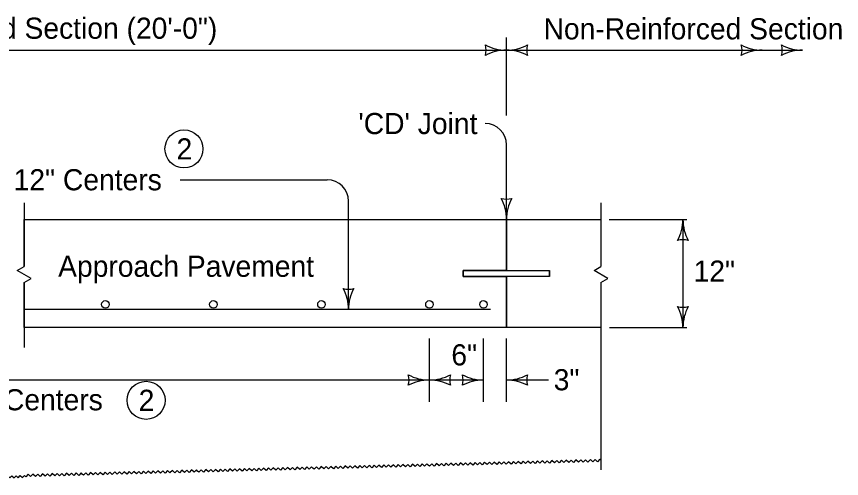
# Model space of a CAD drawing. Extents: x 8925 to 81668, y 4369 to 11918.
# Drawn here: x 12429 to 13210, y 11481 to 11918 of the extents above; entities that cross this region are included whole.
import ezdxf

# ---------------------------------------------------------------- set-up
doc = ezdxf.new("R2010")
doc.units = 0
for name, color, linetype in [('dsnShtPlotShapeBatchPrint', 7, 'Continuous'), ('dsnStdBorder', 7, 'Continuous'), ('Level 3', 7, 'Continuous')]:
    doc.layers.add(name, color=color, linetype=linetype)

msp = doc.modelspace()

# ---------------------------------------------------------------- linework, layer by layer
at = {"layer": 'dsnShtPlotShapeBatchPrint'}
for p, q in [((12892.98, 11824.26), (12892.98, 11897.97)), ((11924.35, 11885.92), (12892.98, 11885.92)), ((12892.98, 11885.92), (13173.42, 11885.92)), ((12892.98, 11725.71), (12892.98, 11796.29)), ((12583.92, 11763.32), (12723.11, 11763.32)), ((12743.32, 11640.46), (12743.32, 11743.11)), ((12436.26, 11681.27), (12436.26, 11725.71)), ((12436.26, 11725.71), (12892.98, 11725.71)), ((12436.26, 11725.71), (12892.98, 11725.71)), ((12892.98, 11725.71), (12892.98, 11677.4)), ((12892.98, 11725.71), (12982.02, 11725.71)), ((12990.13, 11725.71), (13063.96, 11725.71)), ((13060.14, 11725.71), (13060.14, 11623.41)), ((12436.26, 11681.27), (12436.26, 11681.27)), ((12892.98, 11677.4), (12852.06, 11677.4)), ((12852.06, 11677.4), (12852.06, 11671.72)), ((12852.06, 11677.4), (12852.06, 11671.72)), ((12933.9, 11671.72), (12933.9, 11677.4)), ((12436.26, 11623.41), (12436.26, 11666.11)), ((12852.06, 11671.72), (12892.98, 11671.72)), ((12892.98, 11671.72), (12892.98, 11623.41)), ((12892.98, 11623.41), (12892.98, 11671.72)), ((12892.98, 11623.41), (12436.26, 11623.41)), ((12892.98, 11623.41), (12436.26, 11623.41)), ((12982.52, 11623.41), (12892.98, 11623.41)), ((12990.63, 11623.41), (13063.96, 11623.41)), ((12820.04, 11552.95), (12820.04, 11612.92)), ((12871.2, 11552.95), (12871.2, 11612.92)), ((12892.98, 11552.95), (12892.98, 11612.92)), ((12820.04, 11573.73), (11997.28, 11573.73)), ((12871.2, 11573.73), (12820.04, 11573.73)), ((12932.75, 11573.73), (12892.98, 11573.73))]:
    msp.add_line(p, q, dxfattribs=at)
for points in [[(12436.26, 11666.11), (12442.82, 11669.89), (12429.69, 11677.49), (12436.26, 11681.27)], [(12818.88, 11493.3), (12817.71, 11494.42), (12815.49, 11492.08), (12813.16, 11494.3), (12810.94, 11491.96), (12808.6, 11494.18), (12806.39, 11491.85), (12804.05, 11494.06), (12801.84, 11491.73), (12799.5, 11493.94), (12797.29, 11491.61), (12794.95, 11493.82), (12792.74, 11491.49), (12790.4, 11493.7), (12788.19, 11491.37), (12785.85, 11493.58), (12783.63, 11491.25), (12781.31, 11493.47), (12779.09, 11491.13), (12776.75, 11493.35), (12774.53, 11491.01), (12772.21, 11493.23), (12769.99, 11490.9), (12767.65, 11493.11), (12765.44, 11490.77), (12764.27, 11491.88)], [(12873.48, 11494.74), (12872.32, 11495.84), (12870.1, 11493.51), (12867.77, 11495.72), (12865.55, 11493.39), (12863.21, 11495.6), (12861, 11493.27), (12858.66, 11495.49), (12856.45, 11493.15), (12854.11, 11495.37), (12851.9, 11493.03), (12849.56, 11495.24), (12847.35, 11492.92), (12845.01, 11495.13), (12842.8, 11492.8), (12840.46, 11495.01), (12838.25, 11492.68), (12835.91, 11494.89), (12833.7, 11492.56), (12831.36, 11494.77), (12829.14, 11492.44), (12826.81, 11494.66), (12824.59, 11492.32), (12822.26, 11494.53), (12820.04, 11492.21), (12818.88, 11493.3)], [(12928.09, 11496.16), (12926.92, 11497.27), (12924.71, 11494.93), (12922.37, 11497.15), (12920.15, 11494.82), (12917.82, 11497.03), (12915.6, 11494.7), (12913.27, 11496.91), (12911.05, 11494.58), (12908.72, 11496.79), (12906.5, 11494.46), (12904.17, 11496.68), (12901.95, 11494.34), (12899.62, 11496.55), (12897.4, 11494.22), (12895.07, 11496.43), (12892.85, 11494.11), (12890.52, 11496.32), (12888.3, 11493.98), (12885.97, 11496.2), (12883.75, 11493.86), (12881.42, 11496.08), (12879.2, 11493.75), (12876.87, 11495.96), (12874.65, 11493.63), (12873.48, 11494.74)], [(12982.7, 11497.59), (12981.53, 11498.69), (12979.31, 11496.36), (12976.98, 11498.58), (12974.76, 11496.24), (12972.43, 11498.45), (12970.21, 11496.13), (12967.88, 11498.34), (12965.66, 11496), (12963.33, 11498.22), (12961.11, 11495.88), (12958.78, 11498.1), (12956.56, 11495.77), (12954.23, 11497.98), (12952.01, 11495.65), (12949.68, 11497.86), (12947.46, 11495.53), (12945.12, 11497.74), (12942.91, 11495.41), (12940.57, 11497.63), (12938.36, 11495.29), (12936.03, 11497.5), (12933.81, 11495.17), (12931.47, 11497.39), (12929.26, 11495.05), (12928.09, 11496.16)], [(12545.84, 11486.18), (12544.67, 11487.28), (12542.46, 11484.95), (12540.12, 11487.17), (12537.91, 11484.83), (12535.56, 11487.05), (12533.36, 11484.71), (12531.02, 11486.93), (12528.8, 11484.6), (12526.47, 11486.81), (12524.25, 11484.48), (12521.92, 11486.69), (12519.7, 11484.36), (12517.37, 11486.57), (12515.15, 11484.24), (12512.82, 11486.45), (12510.6, 11484.12), (12508.26, 11486.33), (12506.05, 11484), (12503.72, 11486.22), (12501.5, 11483.88), (12499.17, 11486.09), (12496.95, 11483.76), (12494.62, 11485.98), (12492.4, 11483.65), (12491.23, 11484.75)], [(12600.45, 11487.61), (12599.28, 11488.71), (12597.06, 11486.38), (12594.73, 11488.59), (12592.51, 11486.26), (12590.18, 11488.47), (12587.96, 11486.14), (12585.63, 11488.35), (12583.41, 11486.02), (12581.07, 11488.24), (12578.86, 11485.9), (12576.53, 11488.12), (12574.31, 11485.79), (12571.97, 11488), (12569.76, 11485.67), (12567.42, 11487.88), (12565.21, 11485.55), (12562.88, 11487.76), (12560.66, 11485.43), (12558.32, 11487.64), (12556.11, 11485.31), (12553.77, 11487.52), (12551.56, 11485.19), (12549.22, 11487.4), (12547, 11485.07), (12545.84, 11486.18)], [(12655.05, 11489.03), (12653.89, 11490.14), (12651.67, 11487.81), (12649.34, 11490.02), (12647.12, 11487.69), (12644.78, 11489.9), (12642.57, 11487.57), (12640.24, 11489.78), (12638.02, 11487.45), (12635.68, 11489.66), (12633.47, 11487.33), (12631.13, 11489.54), (12628.92, 11487.21), (12626.58, 11489.42), (12624.37, 11487.09), (12622.03, 11489.3), (12619.82, 11486.97), (12617.48, 11489.18), (12615.27, 11486.86), (12612.93, 11489.07), (12610.71, 11486.73), (12608.38, 11488.95), (12606.17, 11486.62), (12603.83, 11488.83), (12601.61, 11486.5), (12600.45, 11487.61)], [(12709.66, 11490.46), (12708.49, 11491.56), (12706.28, 11489.23), (12703.94, 11491.45), (12701.73, 11489.11), (12699.39, 11491.32), (12697.18, 11489), (12694.84, 11491.21), (12692.62, 11488.88), (12690.29, 11491.09), (12688.07, 11488.75), (12685.75, 11490.97), (12683.52, 11488.64), (12681.19, 11490.85), (12678.97, 11488.52), (12676.64, 11490.73), (12674.42, 11488.4), (12672.09, 11490.61), (12669.87, 11488.28), (12667.54, 11490.49), (12665.32, 11488.16), (12662.99, 11490.38), (12660.77, 11488.04), (12658.44, 11490.26), (12656.22, 11487.92), (12655.05, 11489.03)], [(12764.27, 11491.88), (12763.1, 11492.99), (12760.89, 11490.66), (12758.55, 11492.87), (12756.33, 11490.54), (12754, 11492.75), (12751.78, 11490.42), (12749.45, 11492.63), (12747.23, 11490.3), (12744.9, 11492.51), (12742.68, 11490.18), (12740.35, 11492.4), (12738.13, 11490.06), (12735.8, 11492.28), (12733.58, 11489.94), (12731.25, 11492.16), (12729.03, 11489.83), (12726.7, 11492.04), (12724.48, 11489.71), (12722.15, 11491.92), (12719.93, 11489.59), (12717.59, 11491.8), (12715.38, 11489.47), (12713.04, 11491.68), (12710.83, 11489.35), (12709.66, 11490.46)], [(12399.92, 11481.56), (12400.78, 11482.47), (12402.82, 11480.54), (12404.75, 11482.57), (12406.79, 11480.64), (12408.72, 11482.68), (12410.75, 11480.75), (12412.69, 11482.78), (12414.72, 11480.85), (12416.65, 11482.89), (12418.69, 11480.96), (12420.62, 11482.99), (12422.66, 11481.06), (12424.59, 11483.09), (12426.63, 11481.16), (12428.56, 11483.2), (12430.59, 11481.27), (12432.52, 11483.3), (12434.56, 11481.37), (12436.49, 11483.4), (12437.51, 11482.44)], [(12491.23, 11484.75), (12490.06, 11485.86), (12487.84, 11483.52), (12485.51, 11485.74), (12483.29, 11483.41), (12480.96, 11485.62), (12478.75, 11483.29), (12476.41, 11485.5), (12474.2, 11483.17), (12471.86, 11485.38), (12469.65, 11483.05), (12467.31, 11485.26), (12465.1, 11482.93), (12462.76, 11485.14), (12460.54, 11482.81), (12458.21, 11485.03), (12455.99, 11482.7), (12453.66, 11484.91), (12451.44, 11482.58), (12449.11, 11484.79), (12446.89, 11482.46), (12444.55, 11484.67), (12442.34, 11482.34), (12440.01, 11484.55), (12437.79, 11482.22), (12436.63, 11483.32)]]:
    msp.add_lwpolyline(points, dxfattribs=at)
for centre in [(12872.77, 11796.29), (12723.11, 11743.11)]:
    msp.add_arc(centre, 20.21, 0, 90, dxfattribs=at)
at = {"layer": 'dsnStdBorder'}
for p, q in [((12436.26, 11741.35), (12436.26, 11681.27)), ((12982.52, 11741.35), (12982.52, 11681.27)), ((12892.98, 11677.4), (12892.98, 11725.71)), ((12852.06, 11671.72), (12852.06, 11677.4)), ((12852.06, 11677.4), (12933.9, 11677.4)), ((12933.9, 11677.4), (12933.9, 11671.72)), ((12436.26, 11666.11), (12436.26, 11604.56)), ((12933.9, 11671.72), (12852.06, 11671.72)), ((12892.98, 11623.41), (12892.98, 11671.72)), ((12982.52, 11666.11), (12982.52, 11488.87)), ((12877.91, 11640.46), (12436.26, 11640.46))]:
    msp.add_line(p, q, dxfattribs=at)
for points in [[(12436.26, 11666.11), (12442.82, 11669.89), (12429.69, 11677.49), (12436.26, 11681.27)], [(12982.52, 11666.11), (12989.08, 11669.89), (12975.95, 11677.49), (12982.52, 11681.27)]]:
    msp.add_lwpolyline(points, dxfattribs=at)
for centre, radius in [((12587.55, 11792.51), 18), ((12513.13, 11645.36), 3.55), ((12615.43, 11645.36), 3.55), ((12717.74, 11645.36), 3.55), ((12820.04, 11645.36), 3.55), ((12871.2, 11645.36), 3.55), ((12551.66, 11554.53), 18)]:
    msp.add_circle(centre, radius, dxfattribs=at)
for centre, radius, start, end in [((13017.64, 11725.71), 42.5, 331.92751, 360), ((13017.64, 11725.71), 42.5, 331.92751, 360), ((13102.64, 11725.71), 42.5, 180, 208.07249), ((13102.64, 11725.71), 42.5, 180, 208.07249), ((13060.14, 11690.08), 16.42, 72.26665, 107.73335), ((13060.14, 11690.08), 16.42, 72.26665, 107.73335), ((13060.14, 11659.04), 16.42, 252.26665, 287.73335), ((13017.64, 11623.41), 42.5, 360, 28.07249), ((13102.64, 11623.41), 42.5, 151.92751, 180)]:
    msp.add_arc(centre, radius, start, end, dxfattribs=at)
at = {"layer": 'Level 3'}
for centre, radius, start, end in [((12857.34, 11885.92), 16.42, 342.26665, 17.73335), ((12892.98, 11928.42), 42.5, 241.92751, 270), ((12892.98, 11843.42), 42.5, 90, 118.07249), ((12892.98, 11928.42), 42.5, 270, 298.07249), ((12892.98, 11843.42), 42.5, 61.92751, 90), ((12928.61, 11885.92), 16.42, 162.26665, 197.73335), ((13099.68, 11885.92), 16.42, 342.26665, 17.73335), ((13135.31, 11928.42), 42.5, 241.92751, 270), ((13135.31, 11843.42), 42.5, 90, 118.07249), ((13137.79, 11885.92), 16.42, 342.26665, 17.73335), ((13173.42, 11928.42), 42.5, 241.92751, 270), ((13173.42, 11843.42), 42.5, 90, 118.07249), ((12892.98, 11761.35), 16.42, 252.26665, 287.73335), ((12850.48, 11725.71), 42.5, 360, 28.07249), ((12935.48, 11725.71), 42.5, 151.92751, 180), ((12743.32, 11676.1), 16.42, 252.26665, 287.73335), ((12700.82, 11640.46), 42.5, 360, 28.07249), ((12785.82, 11640.46), 42.5, 151.92751, 180), ((12784.41, 11573.73), 16.42, 342.26665, 17.73335), ((12820.04, 11616.23), 42.5, 241.92751, 270), ((12820.04, 11531.23), 42.5, 90, 118.07249), ((12820.04, 11616.23), 42.5, 270, 298.07249), ((12820.04, 11531.23), 42.5, 61.92751, 90), ((12855.68, 11573.73), 16.42, 162.26665, 197.73335), ((12835.56, 11573.73), 16.42, 342.26665, 17.73335), ((12871.2, 11616.23), 42.5, 241.92751, 270), ((12871.2, 11531.23), 42.5, 90, 118.07249), ((12892.98, 11616.23), 42.5, 270, 298.07249), ((12892.98, 11531.23), 42.5, 61.92751, 90), ((12928.61, 11573.73), 16.42, 162.26665, 197.73335)]:
    msp.add_arc(centre, radius, start, end, dxfattribs=at)

# ---------------------------------------------------------------- texts
at = {"layer": 'dsnShtPlotShapeBatchPrint'}
for s, p in [('Single Reinforced Section (20\'-0")', (12218, 11896.76)), ('Non-Reinforced Section', (12928.11, 11896.18)), ("'CD' Joint", (12752.72, 11806.5)), ('2', (12580.53, 11782.51)), ('#5 Bars At 12" Centers', (12293.93, 11753.32)), ('Approach Pavement', (12468.38, 11671.45)), ('12"', (13070.22, 11666.83)), ('6"', (12840.79, 11587.58)), ('3"', (12937.73, 11564.03)), ('#5 Bars At 12" max. Centers', (12172.67, 11545.06)), ('2', (12544.64, 11544.53))]:
    msp.add_text(s, height=20, dxfattribs=at).set_placement(p)

doc.saveas('drawing.dxf')
